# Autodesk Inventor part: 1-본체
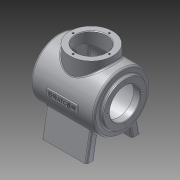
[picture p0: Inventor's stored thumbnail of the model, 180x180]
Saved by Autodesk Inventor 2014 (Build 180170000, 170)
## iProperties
Created: 2015-01
Part Number: 1-본체
Material: Aluminum 6061
Document SubType Name: Modeling
Designer: user
Density: 2.71 g/cm^3
Appearance: Aluminum - Flat
Mass: 1023.02 g
Surface Area: 1061.45 cm^2
Volume: 377.498 cm^3
Author: user
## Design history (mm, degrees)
sketch "Sketch1"
  geometry: C1 r 50 at (0, 0); 1 further point
  constraints: 1 centre point, 1 coincident
  dimensions: "d0" = 100 diameter of C1
extrude "Extrusion1" new body sketch "Sketch1" distance "d1" = 112; taper "d2" = 0 deg
sketch "Sketch2"
  geometry: C1 r 50 at (0, 0) reference; C2 r 38 at (0, 0)
  constraints: 1 centre point, 1 coincident
  dimensions: "d3" = 76 diameter of C2
extrude "Extrusion2" join sketch "Sketch2" distance "d4" = 5; taper "d5" = 0 deg
sketch "Sketch3"
  geometry: C1 r 50 at (0, 0) reference; C2 r 38 at (0, 0)
  constraints: 1 centre point, 1 coincident
  dimensions: "d6" = 76 diameter of C2
extrude "Extrusion3" join sketch "Sketch3" distance "d7" = 5; taper "d8" = 0 deg
workplane "Work Plane1"
sketch "Sketch4"
  geometry: C1 r 45 at (0, 0); 1 further point
  constraints: 1 centre point, 1 coincident
  dimensions: "d10" = 90 diameter of C1
extrude "Extrusion4" cut sketch "Sketch4" distance "d11" = 97; taper "d12" = 0 deg
workplane "Work Plane2"
workplane "Work Plane3"
sketch "Sketch5"
  geometry: L1 (0, 0)-(0, -80); L2 (33.284, -80)-(47.5, -80); L3 (47.5, -80)-(38.927, -31.38); L4 (47.5, -80)-(128.734, -80); L5 (33.284, -80)-(26.639, -42.313); L6 (-47.5, -80)-(-38.927, -31.38); L7 (-33.284, -80)-(-26.639, -42.313); L8 (-33.284, -80)-(-47.5, -80); A1 r 50 centre (0, 0) between (26.639, -42.313) and (38.927, -31.38) reference; A2 r 50 centre (0, 0) between (26.639, -42.313) and (38.927, -31.38); A3 r 50 centre (0, 0) between (-26.639, -42.313) and (-38.927, -31.38); 1 further point
  constraints: 16 end point, 6 point on circle, 4 symmetric about line, 2 centre point, 1 coincident, 1 horizontal, 1 parallel, 1 perpendicular, 1 vertical, 1 other
  dimensions: "d15" = 80 distance of L1.start L1.end; "d16" = 47.5 distance of L1.end L2.end; "d17" = 100 deg angle of L4 L3; "d18" = 14 distance between parallel lines of L3 L5
extrude "Extrusion5" join sketch "Sketch5" distance "d19" = 80; taper "d20" = 0 deg
sketch "Sketch6"
  geometry: C1 r 38 at (0, 0) reference; C2 r 27 at (0, 0)
  constraints: 1 centre point, 1 coincident
  dimensions: "d21" = 54 diameter of C2
hole "Hole1" sketch "Sketch6" at (0, 0) diameter "d22" = 54; stored, may be unused: countersink angle "d26" = 90 deg, drill point angle "d28" = 118 deg; dims "d23" = 6, "d24" = 4, "d25" = 2, "d27" = 8
sketch "Sketch7" dims "d29" = 64
  geometry: C1 r 38 at (0, 0) reference; C2 r 4.365 at (0, 32); 1 further point
  constraints: 1 centre point, 1 coincident, 1 vertical alignment, 2 other
hole "Hole2" sketch "Sketch7" at (0, 32) diameter "d30" = 3.242; stored, may be unused: countersink angle "d34" = 90 deg, drill point angle "d36" = 118 deg; dims "d31" = 8, "d32" = 4, "d33" = 2, "d35" = 10
workaxis "Work Axis1"
pattern_circular "Circular Pattern1" dims angle "d38" = 360 deg
workplane "Work Plane4"
mirror "Mirror1"
workplane "Work Plane6"
sketch "Sketch9"
  geometry: L1 (-50, 0)-(50, 0) reference; L2 (50, 112)-(-50, 112) reference; L3 (-38, -5)-(38, -5) reference; L4 (0, -5)-(0, 57); L5 (38, 117)-(-38, 117) reference; C1 r 38 at (0, 57); 1 further point
  constraints: 2 end point, 1 centre point, 1 coincident, 1 midpoint, 1 perpendicular
  dimensions: "d62" = 62 distance of L4.start L4.end; "d63" = 76 diameter of C1
extrude "Extrusion6" join sketch "Sketch9" distance "d46" = 40; taper "d47" = 0 deg
sketch "Sketch12" dims "d64" = 64
  geometry: C1 r 38 at (0, 0) reference; C2 r 7.426 at (0, 32); 2 further points
  constraints: 1 centre point, 1 coincident, 1 vertical alignment, 2 other
hole "Hole4" sketch "Sketch12" at (0, 32) diameter "d65" = 3.242; stored, may be unused: countersink angle "d69" = 90 deg, drill point angle "d71" = 118 deg; dims "d66" = 8, "d67" = 4, "d68" = 2, "d70" = 10
sketch "Sketch13"
  geometry: C1 r 38 at (0, 0) reference; C2 r 27 at (0, 0); 1 further point
  constraints: 1 centre point, 1 coincident
  dimensions: "d72" = 54 diameter of C2
extrude "Extrusion8" cut sketch "Sketch13" distance "d73" = 40; taper "d74" = 0 deg
pattern_circular "Circular Pattern3" dims angle "d76" = 360 deg
sketch "Sketch14"
  geometry: L1 (-45, 8)-(45, 8) reference; L2 (-45, 105)-(45, 105) reference; L3 (0, 105)-(0, 8); L4 (0, 8)-(45, 8); L5 (45, 8)-(45, 105); L6 (45, 105)-(0, 105); 2 further points
  constraints: 8 end point, 2 midpoint, 2 perpendicular, 1 other
revolve "Revolution1" sketch "Sketch14" stored, may be unused: angle "d78" = 90 deg
workplane "Work Plane10"
sketch "Sketch15"
  geometry: L1 (106.411, 62)-(182.411, 62) reference; L2 (82.411, 38)-(82.411, -38) reference; L3 (117.411, 6)-(171.411, 6); L4 (171.411, 6)-(171.411, -6); L5 (171.411, -6)-(117.411, -6); L6 (117.411, -6)-(117.411, 6); 1 further point
  constraints: 8 end point, 2 parallel, 1 horizontal, 1 perpendicular
  dimensions: "d82" = 54 distance of L4.end L5.end; "d83" = 12 distance of L3.end L4.end
extrude "Extrusion9" join sketch "Sketch15" stored distance "d84" = 4; taper "d85" = 0 deg
sketch "Sketch16"
  geometry: L1 (119.524, 3.602)-(169.299, 3.602); L2 (169.299, 3.602)-(169.299, -3.602); L3 (169.299, -3.602)-(119.524, -3.602); L4 (119.524, -3.602)-(119.524, 3.602); 1 further point
  constraints: 2 other
emboss "Emboss1" sketch "Sketch16" dims "d0" = 100, "d10" = 90, "d86" = 0.5, "d87" = 0
fillet "Fillet1" dims "d88" = 3
fillet "Fillet2" dims "d89" = 3
fillet "Fillet3" dims "d90" = 3
fillet "Fillet4" dims "d91" = 3
fillet "Fillet5" dims "d92" = 3
fillet "Fillet6" dims "d93" = 3
fillet "Fillet7" dims "d94" = 3
chamfer "Chamfer1" distance "d95" = 1; stored, may be unused: second distance "d96" = 2, angle "d97" = 45 deg
chamfer "Chamfer2" distance "d98" = 1; stored, may be unused: second distance "d99" = 2, angle "d100" = 45 deg
body "Solid1"
node "Projected Loop1"
other parameters: "d9" = -7, "d13" = 0, "d14" = -21, "d40" = -56
